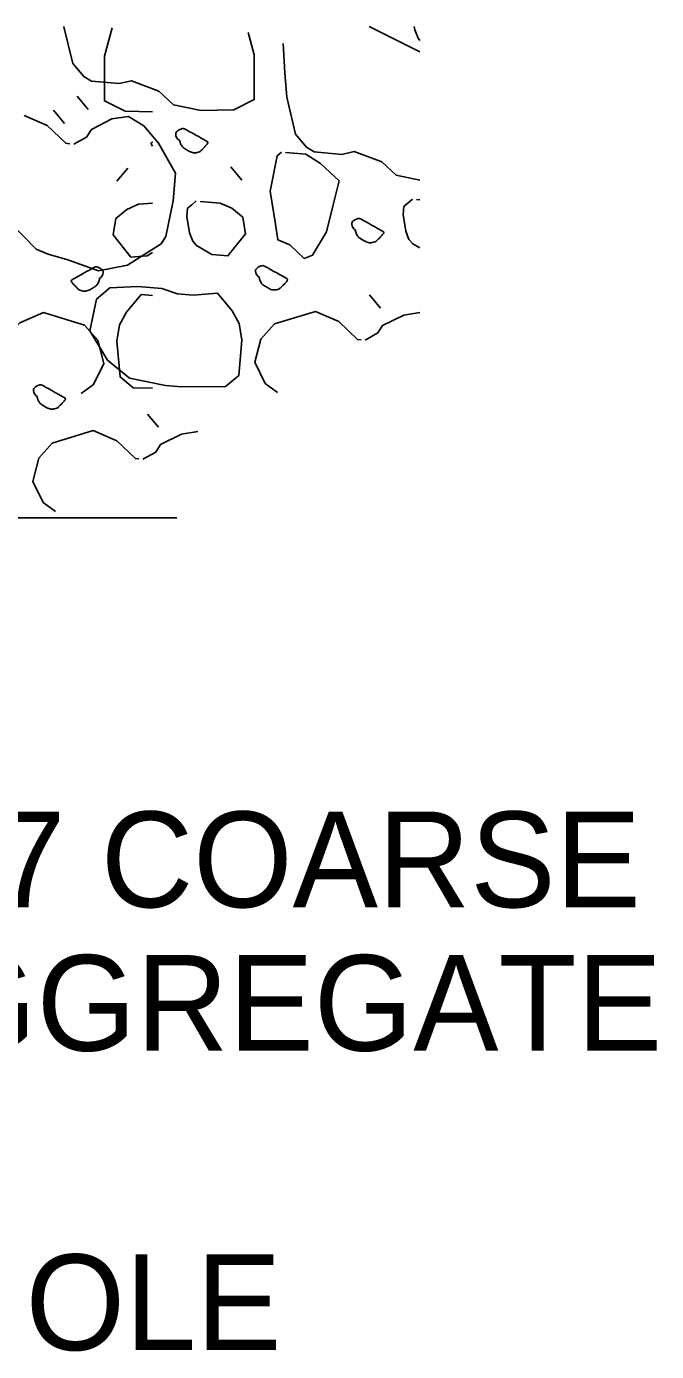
# Model space of a CAD drawing. Extents: x 1299104.8 to 1299141.6, y 239639.8 to 239661.8.
# Drawn here: x 1299117.6 to 1299118.391, y 239645.859 to 239647.521 of the extents above; entities that cross this region are included whole.
import ezdxf

# ---------------------------------------------------------------- set-up
doc = ezdxf.new("R2010")
doc.units = 0
doc.layers.add('DIM TXT', color=7, linetype='Continuous')

msp = doc.modelspace()

# ---------------------------------------------------------------- linework, layer by layer
at = {"layer": 'DIM TXT'}
for p, q in [((1299118.0303, 239647.5212), (1299118.0937, 239647.4895)), ((1299117.6637, 239647.4338), (1299117.6775, 239647.4173)), ((1299117.6341, 239647.4161), (1299117.648, 239647.3996)), ((1299117.7273, 239647.3436), (1299117.7135, 239647.3271)), ((1299117.8567, 239647.3452), (1299117.8705, 239647.3286)), ((1299118.0896, 239647.3042), (1299118.0937, 239647.3039)), ((1299118.0306, 239647.1845), (1299118.0445, 239647.168)), ((1299117.7519, 239647.035), (1299117.7657, 239647.0185)), ((1299116.9623, 239646.905), (1299117.7887, 239646.905)), ((1299117.0354, 239646.905), (1299117.7887, 239646.905))]:
    msp.add_line(p, q, dxfattribs=at)
for points in [[(1299117.8783, 239647.5136), (1299117.8859, 239647.4856), (1299117.886, 239647.4296), (1299117.8602, 239647.4166), (1299117.8195, 239647.4158), (1299117.7845, 239647.4232), (1299117.7664, 239647.44), (1299117.7319, 239647.4532), (1299117.7164, 239647.4496), (1299117.6817, 239647.4525), (1299117.6721, 239647.4585), (1299117.6583, 239647.4749), (1299117.6471, 239647.5209), (1299117.647, 239647.5212)], [(1299118.0937, 239647.5035), (1299118.0916, 239647.5066), (1299118.0873, 239647.5172), (1299118.0867, 239647.5212)], [(1299117.7078, 239647.5197), (1299117.6981, 239647.484), (1299117.698, 239647.428), (1299117.7238, 239647.415), (1299117.7583, 239647.4144)], [(1299118.0937, 239647.3283), (1299118.0641, 239647.3346), (1299118.046, 239647.3514), (1299118.0115, 239647.3646), (1299117.996, 239647.3609), (1299117.9613, 239647.364), (1299117.9517, 239647.3698), (1299117.9379, 239647.3862), (1299117.9267, 239647.4324), (1299117.9243, 239647.463), (1299117.9222, 239647.5001)], [(1299117.6596, 239647.3738), (1299117.6756, 239647.3826), (1299117.6816, 239647.3922), (1299117.7073, 239647.4053), (1299117.728, 239647.4085), (1299117.7473, 239647.3966), (1299117.7657, 239647.3748), (1299117.7871, 239647.3373), (1299117.7841, 239647.3026), (1299117.7751, 239647.2577), (1299117.7692, 239647.2488), (1299117.7269, 239647.222), (1299117.6907, 239647.2149), (1299117.652, 239647.2285), (1299117.6272, 239647.2357), (1299117.6125, 239647.2421), (1299117.5805, 239647.2747)], [(1299117.5973, 239647.4098), (1299117.6261, 239647.3972), (1299117.6495, 239647.3748), (1299117.6545, 239647.3742)], [(1299117.9253, 239647.3632), (1299117.9505, 239647.361), (1299117.9691, 239647.3492), (1299117.9926, 239647.3275), (1299117.9849, 239647.2977), (1299117.9768, 239647.2636), (1299117.9591, 239647.2345), (1299117.9485, 239647.2304), (1299117.9304, 239647.2472), (1299117.9157, 239647.2536), (1299117.9124, 239647.2735), (1299117.9058, 239647.3148), (1299117.9148, 239647.359), (1299117.9203, 239647.3636)], [(1299118.0937, 239647.2435), (1299118.0848, 239647.2487), (1299118.0801, 239647.2542), (1299118.076, 239647.2647), (1299118.0727, 239647.2853), (1299118.0736, 239647.2954), (1299118.0791, 239647.3), (1299118.0845, 239647.3046)], [(1299117.7583, 239647.2997), (1299117.7407, 239647.2982), (1299117.726, 239647.2918), (1299117.7124, 239647.2804), (1299117.7091, 239647.2598), (1299117.7312, 239647.2319), (1299117.7413, 239647.2328), (1299117.7514, 239647.2337), (1299117.7583, 239647.2377)], [(1299117.8181, 239647.3019), (1299117.8433, 239647.2997), (1299117.858, 239647.2933), (1299117.8716, 239647.282), (1299117.8749, 239647.2613), (1299117.8528, 239647.2334), (1299117.8427, 239647.2344), (1299117.8326, 239647.2352), (1299117.8133, 239647.2464), (1299117.8087, 239647.2519), (1299117.8045, 239647.2624), (1299117.8012, 239647.283), (1299117.8021, 239647.2932), (1299117.8076, 239647.2977), (1299117.8131, 239647.3024)], [(1299117.8092, 239647.1842), (1299117.8399, 239647.1866), (1299117.8583, 239647.1646), (1299117.8671, 239647.1486), (1299117.8703, 239647.128), (1299117.8664, 239647.0833), (1299117.85, 239647.0695), (1299117.7947, 239647.0692), (1299117.7745, 239647.071), (1299117.7296, 239647.08), (1299117.7017, 239647.1028), (1299117.6796, 239647.1396), (1299117.6881, 239647.1794), (1299117.7046, 239647.1933), (1299117.7397, 239647.1953), (1299117.7699, 239647.1926), (1299117.7897, 239647.1859), (1299117.8092, 239647.1842)], [(1299117.7583, 239647.184), (1299117.7441, 239647.185), (1299117.7257, 239647.1631), (1299117.7169, 239647.147), (1299117.7137, 239647.1264), (1299117.7176, 239647.0818), (1299117.734, 239647.068), (1299117.7583, 239647.0678)], [(1299117.6688, 239647.0608), (1299117.6843, 239647.072), (1299117.6973, 239647.0986), (1299117.6897, 239647.1277), (1299117.6728, 239647.1466), (1299117.6213, 239647.1624), (1299117.5919, 239647.1496), (1299117.5684, 239647.1272), (1299117.5641, 239647.1269)], [(1299117.9152, 239647.0623), (1299117.8997, 239647.0736), (1299117.8867, 239647.1001), (1299117.8943, 239647.1292), (1299117.9112, 239647.1481), (1299117.9627, 239647.1639), (1299117.9921, 239647.1512), (1299118.0156, 239647.1288), (1299118.0199, 239647.1284)], [(1299118.025, 239647.128), (1299118.041, 239647.1368), (1299118.0469, 239647.1464), (1299118.0735, 239647.1593), (1299118.0937, 239647.1626)], [(1299117.6365, 239646.9128), (1299117.6209, 239646.9241), (1299117.608, 239646.9506), (1299117.6156, 239646.9797), (1299117.6325, 239646.9986), (1299117.684, 239647.0144), (1299117.7134, 239647.0017), (1299117.7369, 239646.9793), (1299117.7411, 239646.9789)], [(1299117.7463, 239646.9785), (1299117.7623, 239646.9873), (1299117.7682, 239646.9969), (1299117.7947, 239647.0098), (1299117.815, 239647.0131)]]:
    msp.add_lwpolyline(points, dxfattribs=at)
for points in [[(1299117.7923, 239647.3789), (1299117.7927, 239647.3766), (1299117.7934, 239647.3744), (1299117.7946, 239647.3722), (1299117.7959, 239647.37), (1299117.7978, 239647.3687), (1299117.8, 239647.3673), (1299117.8044, 239647.3644), (1299117.8096, 239647.3623), (1299117.8141, 239647.3632), (1299117.8173, 239647.3637), (1299117.82, 239647.3663), (1299117.8227, 239647.369), (1299117.825, 239647.3715), (1299117.8289, 239647.3759), (1299117.8263, 239647.3774), (1299117.8233, 239647.3792), (1299117.8202, 239647.3809), (1299117.8172, 239647.3826), (1299117.8114, 239647.3858), (1299117.8057, 239647.3889), (1299117.7999, 239647.392), (1299117.7969, 239647.3937), (1299117.7925, 239647.3924), (1299117.7896, 239647.3901), (1299117.7863, 239647.3875), (1299117.7887, 239647.3804), (1299117.7921, 239647.3782)], [(1299117.7583, 239647.3711), (1299117.7569, 239647.373), (1299117.7562, 239647.375), (1299117.7579, 239647.376), (1299117.7581, 239647.3761), (1299117.7583, 239647.3762)], [(1299118.0128, 239647.2661), (1299118.0132, 239647.2637), (1299118.0139, 239647.2615), (1299118.0151, 239647.2593), (1299118.0164, 239647.2571), (1299118.0183, 239647.2559), (1299118.0205, 239647.2545), (1299118.0249, 239647.2517), (1299118.0301, 239647.2496), (1299118.0347, 239647.2504), (1299118.0378, 239647.2509), (1299118.0405, 239647.2534), (1299118.0432, 239647.2562), (1299118.0456, 239647.2586), (1299118.0494, 239647.2629), (1299118.0468, 239647.2645), (1299118.0439, 239647.2663), (1299118.0408, 239647.268), (1299118.0377, 239647.2697), (1299118.032, 239647.2729), (1299118.0262, 239647.2761), (1299118.0205, 239647.2792), (1299118.0174, 239647.2809), (1299118.0129, 239647.2795), (1299118.0101, 239647.2772), (1299118.0069, 239647.2744), (1299118.01, 239647.2676), (1299118.0134, 239647.2653)], [(1299117.8921, 239647.2069), (1299117.8925, 239647.2045), (1299117.8932, 239647.2023), (1299117.8945, 239647.2002), (1299117.8957, 239647.1979), (1299117.8977, 239647.1967), (1299117.8999, 239647.1953), (1299117.9043, 239647.1925), (1299117.9095, 239647.1904), (1299117.914, 239647.1912), (1299117.9172, 239647.1917), (1299117.9198, 239647.1943), (1299117.9225, 239647.197), (1299117.9249, 239647.1994), (1299117.9287, 239647.2038), (1299117.9261, 239647.2054), (1299117.9231, 239647.2071), (1299117.9201, 239647.2088), (1299117.9171, 239647.2105), (1299117.9113, 239647.2137), (1299117.9056, 239647.2169), (1299117.8999, 239647.2201), (1299117.8968, 239647.2218), (1299117.8922, 239647.2204), (1299117.8895, 239647.218), (1299117.8862, 239647.2153), (1299117.8893, 239647.2084), (1299117.8928, 239647.2061)], [(1299117.6919, 239647.2054), (1299117.6915, 239647.203), (1299117.6908, 239647.2008), (1299117.6895, 239647.1986), (1299117.6882, 239647.1964), (1299117.6863, 239647.1952), (1299117.6841, 239647.1938), (1299117.6797, 239647.1909), (1299117.6745, 239647.1888), (1299117.67, 239647.1896), (1299117.6668, 239647.1902), (1299117.6642, 239647.1927), (1299117.6615, 239647.1955), (1299117.6591, 239647.1979), (1299117.6553, 239647.2023), (1299117.6579, 239647.2038), (1299117.6609, 239647.2056), (1299117.6639, 239647.2073), (1299117.6669, 239647.209), (1299117.6727, 239647.2122), (1299117.6784, 239647.2154), (1299117.6841, 239647.2186), (1299117.6872, 239647.2203), (1299117.6918, 239647.2188), (1299117.6945, 239647.2165), (1299117.6978, 239647.2138), (1299117.6947, 239647.2069), (1299117.6912, 239647.2046)], [(1299117.6134, 239647.0574), (1299117.6138, 239647.055), (1299117.6145, 239647.0528), (1299117.6157, 239647.0507), (1299117.617, 239647.0485), (1299117.6189, 239647.0472), (1299117.6211, 239647.0458), (1299117.6256, 239647.043), (1299117.6308, 239647.0409), (1299117.6353, 239647.0417), (1299117.6384, 239647.0422), (1299117.6411, 239647.0448), (1299117.6438, 239647.0475), (1299117.6462, 239647.05), (1299117.65, 239647.0544), (1299117.6474, 239647.0559), (1299117.6444, 239647.0576), (1299117.6414, 239647.0593), (1299117.6383, 239647.061), (1299117.6326, 239647.0642), (1299117.6269, 239647.0674), (1299117.6211, 239647.0706), (1299117.618, 239647.0723), (1299117.6135, 239647.0709), (1299117.6107, 239647.0685), (1299117.6075, 239647.0658), (1299117.6106, 239647.0589), (1299117.6141, 239647.0566)]]:
    msp.add_open_spline(points, degree=3, dxfattribs=at)

# ---------------------------------------------------------------- texts
for s, p in [('#57 COARSE', (1299117.3811, 239646.4165)), ('AGGREGATE', (1299117.3811, 239646.2365)), ('DRAIN HOLE', (1299116.9393, 239645.861))]:
    msp.add_text(s, height=0.12, dxfattribs=at).set_placement(p)

doc.saveas('drawing.dxf')
